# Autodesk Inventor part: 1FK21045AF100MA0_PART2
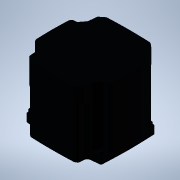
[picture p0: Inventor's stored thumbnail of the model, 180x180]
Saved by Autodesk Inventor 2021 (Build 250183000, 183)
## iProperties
Created: 2025-04
Part Number: 1FK21045AF100MA0_PART2
Material: Generic
Catalog Web Link: www.3dfindit.com
Description: -Servo synchronous motor
Document SubType Name: Modeling
Designer: psAdmin
Mass: 372.123 g
Surface Area: 313.117 cm^2
Volume: 372.123 cm^3
Density: 1 g/cm^3
Appearance: PSOLRGB-38-46-56
Category: PARTsolutions
Title: 1FK21045AF100MA0_PART2
Author: Cadenas PARTsolutions
Comments: Servo synchronous motor
Sending System: PARTsolutions
Preprocessor: ST-DEVELOPER v19.3
PSOL_IDENT_0: {$CADENAS_DATA/23d-libs/siemens_ag/_cat_/52/6b/1fk21045af100ma0.prj},213 {VTYP=3D},{NB=1FK21045AF100
PSOL_IDENT_1: MA0_PART2},{LINA=1FK21045AF100MA0_PART2},{NN=1FK21045AF100MA0_PART2},{NOPRJ=TRUE},{DATE=19.08.2025 1
PSOL_IDENT_2: 4:00:38},{GEOMDATE=30.07.2025 02:01:45},{VERSION=},{LINEID=10},{WBVAR=},{WBNUMERIC=}  {NB=1FK21045AF
PSOL_IDENT_3: 100MA0_PART2},{LINA=1FK21045AF100MA0_PART2},{KT=DUMMY},{PREVIEW=../../../_pool_/cb/72/p_d211_xx_0043
PSOL_IDENT_4: 4j.png},{DESCSHORT=SIMOTICS S-1FK2 HD, SINAMICS S210 3AC 400V-480V, 2.4 Nm, 3000 rpm},{DESCLONG=SIMO
PSOL_IDENT_5: TICS S-1FK2 HD servo motor M0=2.4 Nm; PN = 0.75 kW at nN=3000 rpm (380-480 V); PN = 0.375 kW at nN=1
PSOL_IDENT_6: 500 rpm (200-240 V); with holding brake; degree of protection IP64; cylindrical shaft D19x40mm; abso
PSOL_IDENT_7: lute encoder 22-bit + 12-bit multiturn (encoder AM22DQC); with OCC interface; plug size M17, rotatab
PSOL_IDENT_8: le; SIMOTICS S-1FK2 servomotorfor a wide range of uses in industrial environments. SIMOTICS S‑1FK2 s
PSOL_IDENT_9: ervomotors are compact synchronous motors with a high dynamic performance that set themselves apart
PSOL_IDENT_10: as a result of their high power density, degree of protection and overload capability. The motors ar
PSOL_IDENT_11: e available in two variants: as High Dynamic variant (highest dynamic performance as a result of the
PSOL_IDENT_12: low intrinsic moment of inertia for applications demanding a high dynamic performance with low move
PSOL_IDENT_13: d masses) - and as Compact variant (precise and stable closed-loop control for medium up to large mo
PSOL_IDENT_14: ved masses as a result of a medium intrinsic moment of inertia). SIMOTICSS‑1FK2 servomotors fully ex
PSOL_IDENT_15: ploit their strengths in a system with the SINAMICSS210 frequency converter and simple connection us
PSOL_IDENT_16: ing the one cable connection (OCC). Advantages include the short control and positioning times, fast
PSOL_IDENT_17: and precise correction of disturbing quantities as well as stable control with a high dynamic perfo
PSOL_IDENT_18: rmance. The servo motors can be configured to address a wide range of requirements. For example with
PSOL_IDENT_19: and without holding brake, IP64 or IP65 degree of protection, singleturn or multiturn absolute enco
PSOL_IDENT_20: ders - to name just a few. Further, the servomotors are available in different shaft heights extendi
PSOL_IDENT_21: ng from 20 to 100. A shaft sealing ring is available to achieve an IP65 degree of protection and for
PSOL_IDENT_22: subsequent mounting at the motor or as spare part. SIMOTICS - the optimum motor for each and every
PSOL_IDENT_23: motion control application.},{INTNO=804766906411},{SUPPLIERALTNO=1FK2104-5AF10-0MA0},{MANUID=1FK2104
PSOL_IDENT_24: 5AF100MA0},{MANUNAME=Siemens},{MANUTYPEDESC=Synchronous motor 1FK2-HD 2.4 NM},{AAU732=SIMOTICS},{AAO
PSOL_IDENT_25: 057=S-1FK2},{AAU734=SIMOTICS S-1FK2 HD servo motor M0=2.4 Nm; PN = 0.75 kW at nN=3000 rpm (380-480 V
PSOL_IDENT_26: ); PN = 0.375 kW at nN=1500 rpm (200-240 V); with holding brake; degree of protection IP64; cylindri
PSOL_IDENT_27: cal shaft D19x40mm; absolute encoder 22-bit + 12-bit multiturn (encoder AM22DQC); with OCC interface
PSOL_IDENT_28: ; plug size M17, rotatable;},{AAW338=Synchronous motor 1FK2-HD 2.4 NM},{AAO742=SIMOTICS},{AAO663=404
PSOL_IDENT_29: 2948693070},{NOCUPEROU=1},{PRICEQUANTITY=1},{QUANTITYMIN=1},{QUANTITYINT=1},{CTN=85015100},{COO=DE},
PSOL_IDENT_30: {AAO676=1FK2104-5AF10-0MA0},{AAO677=Siemens AG},{ORDERUNIT=C62},{CONTENTUNIT=C62}
NB: 1FK21045AF100MA0_PART2
NT: Servo synchronous motor
NBSYN: $MANUID._PART2
LINA: 1FK21045AF100MA0_PART2
CATALOG: SIEMENS
PREVIEW: ../../../_pool_/cb/72/p_d211_xx_00434j.png
DESCSHORT: SIMOTICS S-1FK2 HD, SINAMICS S210 3AC 400V-480V, 2.4 Nm, 3000 rpm
DESCLONG: SIMOTICS S-1FK2 HD servo motor M0=2.4 Nm; PN = 0.75 kW at nN=3000 rpm (380-480 V); PN = 0.375 kW at nN=1500 rpm (200-240 V); with holding brake; degree of prote
INTNO: 804766906411
SUPPLIERALTNO: 1FK2104-5AF10-0MA0
MANUID: 1FK21045AF100MA0
MANUNAME: Siemens
MANUTYPEDESC: Synchronous motor 1FK2-HD 2.4 NM
AAU732: SIMOTICS
AAO057: S-1FK2
AAU734: SIMOTICS S-1FK2 HD servo motor M0=2.4 Nm; PN = 0.75 kW at nN=3000 rpm (380-480 V); PN = 0.375 kW at nN=1500 rpm (200-240 V); with holding brake; degree of prote
AAW338: Synchronous motor 1FK2-HD 2.4 NM
AAO742: SIMOTICS
AAO663: 4042948693070.0
NOCUPEROU: 1
PRICEQUANTITY: 1
QUANTITYMIN: 1
QUANTITYINT: 1
CTN: 85015100
COO: DE
ARTICLENO: 1FK21045AF100MA0_PART2
BOMINFO: 1FK21045AF100MA0_PART2
CREATOR: CADENAS GmbH
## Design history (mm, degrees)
feature "2025_04_17_15_34_52_0192"
body "Solid1"
